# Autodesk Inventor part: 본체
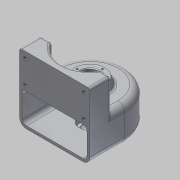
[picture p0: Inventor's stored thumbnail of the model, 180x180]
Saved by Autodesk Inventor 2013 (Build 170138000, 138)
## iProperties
Created: 2015-02
Part Number: 본체
Material: 알루미늄 6061
Document SubType Name: Modeling
Designer: Administrator
Density: 2.71 g/cm^3
Mass: 575.526 g
Surface Area: 706.56 cm^2
Volume: 212.371 cm^3
Author: Administrator
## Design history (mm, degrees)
sketch "스케치1"
  geometry: L1 (50, 0)-(50, -50); L2 (50, -50)-(-50, -50); L3 (-50, -50)-(-50, 0); A1 r 50 centre (0, 0) between (50, 0) and (-50, 0); 2 further points
  constraints: 6 end point, 2 coincident, 2 point on circle, 1 centre point, 1 parallel, 1 vertical
  dimensions: "d3" = 50 distance of L1.start L1.end; "d5" = 50 radius of A1; "d6" = 100 distance of L1.end L2.end; "d7" = 50 distance from line of point (0, 0) L3; "d8" = 50 distance of L2.end L3.end
extrude "돌출1" new body sketch "스케치1" distance "d9" = 50; taper "d10" = 0 deg
feature "쉘1" dims "d30" = 4
sketch "스케치6"
  geometry: L1 (0, 60)-(0, 50); L2 (50, 50)-(0, 50) reference; L3 (0, 60)-(21.36, 60); L4 (21.36, 60)-(25, 50); 1 further point
  constraints: 6 end point, 1 coincident, 1 midpoint, 1 parallel, 1 vertical
  dimensions: "d31" = 10 distance of L1.start L1.end; "d33" = 110 deg angle of L2 L4; "d34" = 50 diameter of L4.end L1
revolve "회전3" sketch "스케치6" stored, may be unused: angle "d35" = 90 deg
sketch "스케치7"
  geometry: C1 r 21.36 at (0, 0) reference; 1 further point
  constraints: 1 coincident
hole "구멍2" sketch "스케치7" at (0, 0) diameter "d36" = 20; stored, may be unused: countersink angle "d40" = 90 deg, drill point angle "d42" = 0 deg; dims "d37" = 6, "d38" = 28, "d39" = 10, "d41" = 4
sketch "스케치8"
  geometry: C1 r 20 at (0, 0); A1 r 50 centre (0, 0) between (50, 0) and (-50, 0) reference
  constraints: 1 centre point, 1 coincident
  dimensions: "d43" = 40 diameter of C1
extrude "돌출2" join sketch "스케치8" distance "d44" = 9; taper "d45" = 0 deg
sketch "스케치9"
  geometry: A1 r 46 centre (0, 0) between (46, 0) and (-46, 0) reference; 1 further point
  constraints: 1 coincident
hole "구멍3" sketch "스케치9" at (0, 0) diameter "d46" = 20; stored, may be unused: countersink angle "d50" = 90 deg, drill point angle "d52" = 0 deg; dims "d47" = 6, "d48" = 28, "d49" = 8, "d51" = 2
sketch "스케치10"
  geometry: L1 (50, -50)-(50, 0) reference; L2 (-50, -50)-(50, -50) reference; L3 (50, -20)-(50, -50); L4 (50, -50)-(-50, -50); L5 (-50, -50)-(-50, -20); L6 (-50, -20)-(-34.641, -20); L7 (34.641, -20)-(50, -20); A1 r 50 centre (0, 0) between (50, 0) and (-50, 0) reference; A2 r 40 centre (0, 0) between (-34.641, -20) and (34.641, -20)
  constraints: 10 end point, 3 parallel, 2 horizontal, 2 perpendicular, 2 point on circle, 1 centre point, 1 coincident
  dimensions: "d53" = 30 distance of L3.start L3.end; "d55" = 100 distance of L3.end L4.end; "d56" = 0 distance between parallel lines of L2 L4; "d57" = 0 distance between parallel lines of L1 L3; "d58" = 80 diameter of A2; "d59" = 15.35898 distance of L5.end L6.end
extrude "돌출3" join sketch "스케치10" distance "d60" = 45; taper "d61" = 0 deg
sketch "스케치11" dims "d62" = 36
  geometry: L1 (0, 0)-(0, 18); C1 r 21.36 at (0, 0) reference; 1 further point
  constraints: 2 coincident, 2 end point, 1 vertical, 1 vertical alignment, 2 other
hole "구멍4" sketch "스케치11" at (0, 18) diameter "d63" = 2.459; stored, may be unused: countersink angle "d67" = 90 deg, drill point angle "d69" = 118 deg; dims "d64" = 6, "d65" = 4, "d66" = 2, "d68" = 9
sketch "스케치13"
  geometry: L1 (4, 46)-(96, 46) reference; L2 (0, 95)-(100, 95) reference; 5 further points
  dimensions: "d73" = 83.5 distance of point (8.25, 86) point (91.75, 86); "d75" = 33 distance of point (91.75, 53) point (91.75, 86); "d76" = 41.75 horizontal distance of point (50, 0) point (8.25, 53); "d77" = 41.75 horizontal distance of point (50, 0) point (8.25, 86); "d78" = 9 distance from line of point (91.75, 86) L2; "d79" = 9 distance from line of point (8.25, 86) L2; "d80" = 7 distance from line of L1 point (91.75, 53); "d81" = 7 distance from line of L1 point (8.25, 53)
hole "구멍5" sketch "스케치13" at (91.75, 86), (91.75, 53), (8.25, 53), (8.25, 86) diameter "d82" = 5.134; stored, may be unused: countersink angle "d86" = 90 deg, drill point angle "d88" = 118 deg; dims "d83" = 10, "d84" = 4, "d85" = 2, "d87" = 13
chamfer "모따기1" distance "d89" = 1; stored, may be unused: second distance "d90" = 2, angle "d91" = 45 deg
fillet "모깎기1" dims "d92" = 0.3
fillet "모깎기2" dims "d93" = 10
fillet "모깎기3" dims "d94" = 3
fillet "모깎기4" dims "d95" = 6
fillet "모깎기5" dims "d96" = 3
fillet "모깎기6" dims "d97" = 3
fillet "모깎기7" dims "d98" = 3
chamfer "모따기2" distance "d99" = 1; stored, may be unused: second distance "d100" = 2, angle "d101" = 45 deg
fillet "모깎기8" dims "d102" = 3
node "작업 평면1"
sketch "스케치14"
  geometry: 2 further points
  constraints: 1 other
  dimensions: "d103" = 25 distance of point (0, 0) point (0, 25); "d104" = 0 horizontal distance of point (0, 0) point (0, 25)
feature "엠보싱1" sketch "스케치14" dims "d105" = 0.5, "d106" = 0
node "솔리드1"
pattern_circular "원형 패턴1" dims angle "d71" = 360 deg
